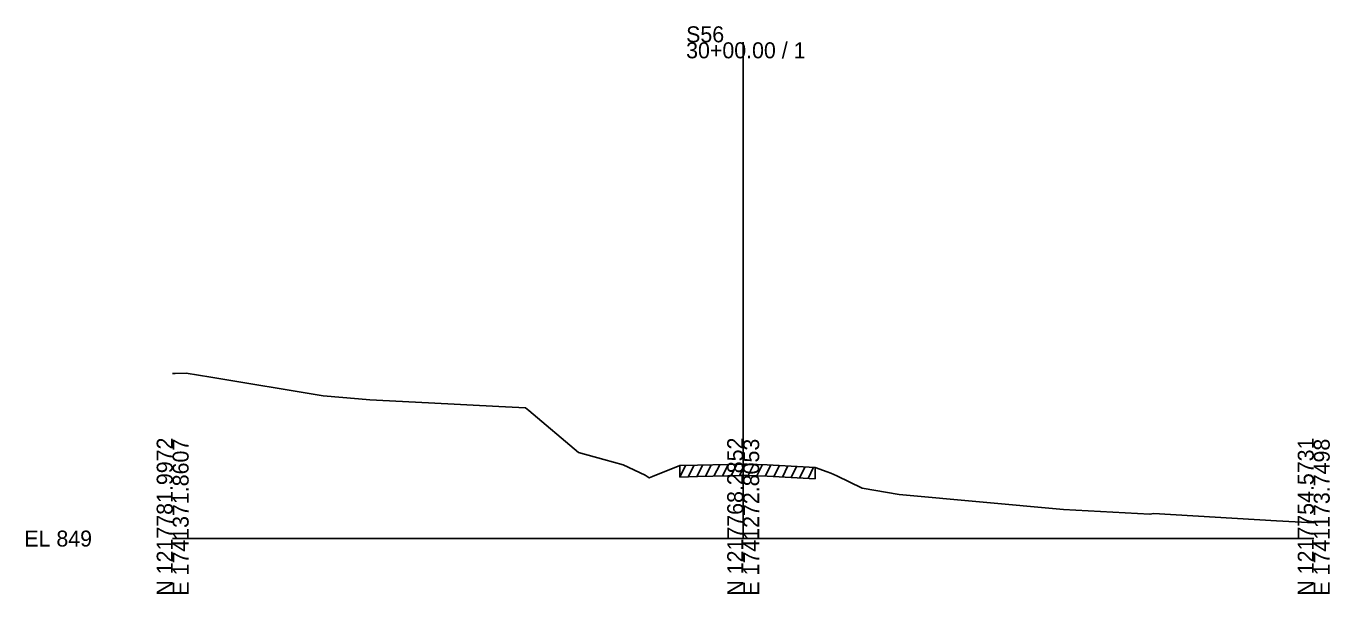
# Model space of a CAD drawing. Extents: x -26 to 1203, y -10 to 19541.
# Drawn here: x -25.7 to 202.8, y 4990.3 to 5089.8 of the extents above; entities that cross this region are included whole.
import ezdxf

# ---------------------------------------------------------------- set-up
doc = ezdxf.new("R2010")
doc.units = 0
for name, color, linetype in [('RD_GPK_XS_Cell', 7, 'Continuous'), ('RD_XS_ExGround', 7, 'Continuous'), ('RD_XS_ExPaveRet', 7, 'Continuous'), ('RD_XS_TX_Elev_EX', 7, 'Continuous')]:
    doc.layers.add(name, color=color, linetype=linetype)

msp = doc.modelspace()

# ---------------------------------------------------------------- linework, layer by layer
at = {"layer": 'RD_GPK_XS_Cell'}
for p, q in [((100, 5000), (100, 5086.92)), ((0, 5000), (100, 5000)), ((100, 5000), (200, 5000))]:
    msp.add_line(p, q, dxfattribs=at)
at = {"layer": 'RD_XS_ExGround'}
msp.add_lwpolyline([(0, 5028.91), (0.45, 5028.92), (2.38, 5028.97), (6.68, 5028.26), (26.36, 5025.02), (32.55, 5024.47), (34.58, 5024.31), (44.87, 5023.8), (57.18, 5023.13), (61.85, 5022.88), (62.41, 5022.41), (71.16, 5015.09), (75.55, 5013.82), (78.99, 5012.92), (82.79, 5011.1), (83.52, 5010.61), (84.13, 5010.89), (88.88, 5012.78), (92.02, 5012.85), (100, 5013.04), (100.67, 5013.06), (104.19, 5012.92), (112.62, 5012.46), (114.71, 5011.71), (115.38, 5011.45), (116.41, 5010.96), (120.84, 5008.85), (127.33, 5007.74), (156.16, 5005.07), (171.3, 5004.26), (171.99, 5004.41), (193.5, 5003.12), (200, 5002.76)], dxfattribs=at)
at = {"layer": 'RD_XS_ExPaveRet'}
for p, q in [((88.88, 5010.78), (89.89, 5012.8)), ((88.88, 5010.78), (88.88, 5012.78)), ((90.38, 5010.81), (91.39, 5012.83)), ((91.88, 5010.84), (92.89, 5012.87)), ((93.38, 5010.88), (94.39, 5012.9)), ((94.88, 5010.92), (95.89, 5012.94)), ((96.38, 5010.95), (97.39, 5012.98)), ((97.88, 5010.99), (98.89, 5013.01)), ((99.38, 5011.03), (100.39, 5013.05)), ((100.88, 5011.05), (101.86, 5013.01)), ((102.38, 5010.99), (103.36, 5012.95)), ((103.88, 5010.93), (104.86, 5012.88)), ((105.38, 5010.85), (106.35, 5012.8)), ((106.88, 5010.77), (107.85, 5012.72)), ((108.38, 5010.69), (109.35, 5012.64)), ((109.88, 5010.61), (110.85, 5012.56)), ((111.38, 5010.53), (112.35, 5012.48)), ((112.62, 5012.46), (112.62, 5010.46)), ((88.88, 5010.78), (92.02, 5010.85)), ((92.02, 5010.85), (100, 5011.04)), ((100, 5011.04), (100.67, 5011.06)), ((100.67, 5011.06), (104.19, 5010.92)), ((104.19, 5010.92), (112.62, 5010.46))]:
    msp.add_line(p, q, dxfattribs=at)

# ---------------------------------------------------------------- texts
at = {"layer": 'RD_GPK_XS_Cell'}
for s, p in [('S56', (90, 5086.92)), ('30+00.00 / 1', (90, 5084.12)), ('EL 849', (-26, 4998.6))]:
    msp.add_text(s, height=2.8, dxfattribs=at).set_placement(p)
for s, p in [('N 1217781.9972', (0, 4990)), ('E 1741371.8607', (2.8, 4990)), ('N 1217768.2852', (100, 4990)), ('E 1741272.8053', (102.8, 4990)), ('N 1217754.5731', (200, 4990)), ('E 1741173.7498', (202.8, 4990))]:
    msp.add_text(s, height=2.8, rotation=90, dxfattribs=at).set_placement(p)
at = {"layer": 'RD_XS_TX_Elev_EX'}
msp.add_text('855.52', height=0.1, rotation=90, dxfattribs=at).set_placement((100.1, 5013.04))

doc.saveas('drawing.dxf')
